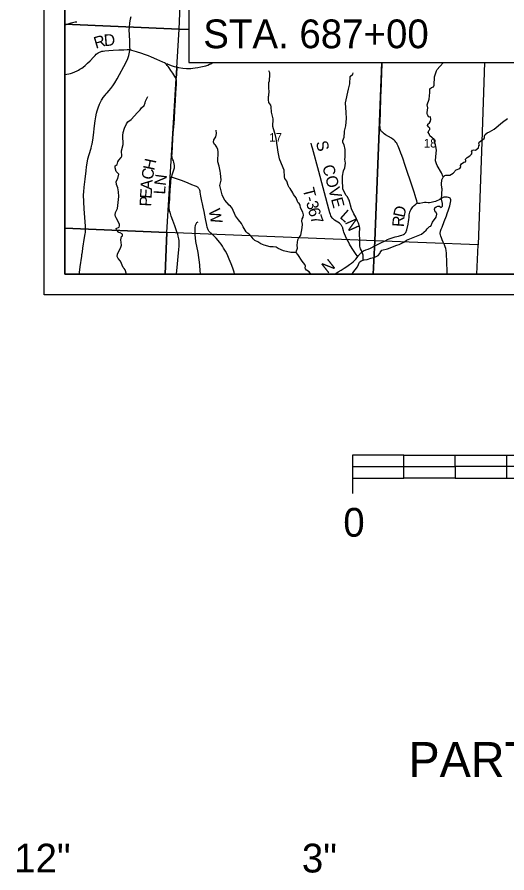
# Model space of a CAD drawing. Extents: x 0 to 34, y 0 to 22.
# Drawn here: x 23.784 to 26.169, y 11.185 to 15.353 of the extents above; entities that cross this region are included whole.
import ezdxf

# ---------------------------------------------------------------- set-up
doc = ezdxf.new("R2010")
doc.units = 0
for name, color, linetype in [('GM_X_Adjacent_County', 7, 'Continuous'), ('GM_X_County', 7, 'Continuous'), ('GM_X_County_Road', 7, 'Continuous'), ('GM_X_County_Road_Text', 7, 'Continuous'), ('GM_X_Minor_River', 7, 'Continuous'), ('GM_X_Section', 7, 'Continuous'), ('GM_X_Section_Text', 7, 'Continuous'), ('GM_X_Township', 7, 'Continuous'), ('GM_X_Township_Road', 7, 'Continuous'), ('GM_X_Township_Road_Text', 7, 'Continuous'), ('SH_Data', 7, 'Continuous'), ('SH_Text', 7, 'Continuous')]:
    doc.layers.add(name, color=color, linetype=linetype)

msp = doc.modelspace()

# ---------------------------------------------------------------- linework, layer by layer
at = {"layer": 'GM_X_Adjacent_County'}
msp.add_lwpolyline([(28.7526, 20.9), (24.0167, 20.9), (24.0167, 14.1), (28.5181, 14.1)], dxfattribs=at)
at = {"layer": 'GM_X_County'}
msp.add_lwpolyline([(28.7526, 20.9), (24.0167, 20.9), (24.0167, 14.1), (28.5181, 14.1)], dxfattribs=at)
at = {"layer": 'GM_X_County_Road'}
for points in [[(24.3339, 15.1942), (24.334, 15.1957), (24.3339, 15.2052), (24.3335, 15.2144), (24.3327, 15.233), (24.3309, 15.2671), (24.3307, 15.2888), (24.3315, 15.3043), (24.3335, 15.3227), (24.3371, 15.3442), (24.34, 15.3563)], [(24.0862, 14.1), (24.0874, 14.1082), (24.0915, 14.1358), (24.0991, 14.1877), (24.0996, 14.1931), (24.1002, 14.1969), (24.1009, 14.2018), (24.102, 14.2098), (24.1047, 14.2273), (24.1132, 14.2796), (24.116, 14.298), (24.1166, 14.304), (24.1173, 14.3102), (24.1176, 14.3195), (24.1173, 14.3275), (24.117, 14.3351), (24.111, 14.4188), (24.1088, 14.4529), (24.1083, 14.487), (24.1088, 14.5025), (24.1105, 14.5241), (24.1153, 14.5642), (24.1198, 14.6044), (24.1223, 14.6228), (24.1253, 14.6411), (24.1294, 14.6623), (24.1348, 14.6834), (24.1441, 14.7146), (24.1466, 14.7234), (24.1484, 14.7309), (24.1491, 14.7342), (24.1514, 14.7452), (24.1526, 14.7526), (24.1563, 14.7771), (24.1618, 14.8231), (24.1647, 14.8477), (24.1672, 14.8662), (24.1704, 14.8845), (24.1734, 14.8964), (24.1787, 14.9109), (24.1857, 14.9282), (24.1922, 14.9422), (24.1956, 14.9486), (24.1983, 14.9529), (24.2036, 14.9605), (24.2131, 14.9725), (24.2187, 14.9794), (24.2225, 14.984), (24.2324, 14.9955), (24.2405, 15.0049), (24.2499, 15.0173), (24.2602, 15.0328), (24.271, 15.0518), (24.2828, 15.0736), (24.3041, 15.1115), (24.3155, 15.1336), (24.3231, 15.1506), (24.3284, 15.1652), (24.3307, 15.1742), (24.3323, 15.1815), (24.3335, 15.1894), (24.3339, 15.1942)], [(24.5097, 15.1242), (24.5065, 15.1268), (24.5027, 15.1293), (24.494, 15.1334), (24.4785, 15.14), (24.4642, 15.1463), (24.4386, 15.1574), (24.4243, 15.1632), (24.404, 15.1708), (24.3923, 15.1748), (24.3657, 15.1832), (24.3425, 15.1906), (24.3339, 15.1942)], [(25.731, 14.4469), (25.7316, 14.4497), (25.7317, 14.4521), (25.7314, 14.4548), (25.7307, 14.4579), (25.7261, 14.4727), (25.7221, 14.4845), (25.7172, 14.4993), (25.7106, 14.52), (25.6723, 14.6346), (25.6636, 14.6608), (25.6573, 14.6782), (25.6527, 14.6897), (25.646, 14.7071), (25.6393, 14.7245), (25.6355, 14.7331), (25.6325, 14.7386), (25.6291, 14.7439), (25.6252, 14.7488), (25.6207, 14.7533), (25.6158, 14.7572), (25.608, 14.7624), (25.5786, 14.7797), (25.5709, 14.7848), (25.566, 14.7886), (25.5615, 14.7927), (25.5595, 14.795), (25.5576, 14.7974), (25.556, 14.7999), (25.5546, 14.8026), (25.5534, 14.8054), (25.5525, 14.8083), (25.5518, 14.8112), (25.5513, 14.8142), (25.551, 14.8263), (25.5518, 14.8388), (25.5535, 14.891), (25.5552, 14.9559), (25.5557, 14.9683), (25.5565, 14.9869), (25.5618, 15.1264), (25.5619, 15.131)], [(24.5582, 15.053), (24.552, 15.0638), (24.5418, 15.08), (24.5329, 15.0927), (24.5242, 15.1057), (24.5193, 15.1125), (24.5152, 15.1176), (24.5116, 15.1218), (24.5097, 15.1242)], [(24.5582, 15.053), (24.5604, 15.0579), (24.5609, 15.0624), (24.5615, 15.0678), (24.5617, 15.0756), (24.5619, 15.0816), (24.5626, 15.0905), (24.5631, 15.0964), (24.5639, 15.1014), (24.5654, 15.1073), (24.5656, 15.1081)], [(24.5362, 14.5738), (24.5407, 14.5887), (24.5473, 14.6093), (24.5501, 14.6181), (24.5508, 14.6234), (24.5508, 14.6304), (24.5497, 14.6385), (24.5473, 14.6463), (24.5452, 14.6523), (24.5429, 14.6571), (24.5408, 14.6617), (24.5396, 14.6652), (24.5387, 14.67), (24.5384, 14.6754), (24.5389, 14.6886), (24.5424, 14.7588), (24.5446, 14.7887), (24.547, 14.8178), (24.5484, 14.834), (24.55, 14.8564), (24.5524, 14.9006), (24.5532, 14.9209), (24.5548, 14.9478), (24.5576, 14.9829), (24.5589, 15.0046), (24.5606, 15.0258), (24.5606, 15.0368), (24.5598, 15.046), (24.5582, 15.053)], [(24.8429, 14.1), (24.8426, 14.1021), (24.8413, 14.1102), (24.8386, 14.1201), (24.8348, 14.1303), (24.8268, 14.1504), (24.8172, 14.1733), (24.8097, 14.1903), (24.8048, 14.201), (24.7989, 14.2126), (24.79, 14.2277), (24.7849, 14.2364), (24.7781, 14.2461), (24.7703, 14.2563), (24.7636, 14.2647), (24.7528, 14.276), (24.7393, 14.29), (24.7282, 14.2997), (24.7249, 14.3031), (24.7228, 14.3051), (24.72, 14.3082), (24.718, 14.3107), (24.7162, 14.3134), (24.7146, 14.3166), (24.7129, 14.321), (24.7116, 14.3248), (24.7105, 14.3289), (24.708, 14.3386), (24.7016, 14.3701), (24.6945, 14.4052), (24.6899, 14.4277), (24.6865, 14.4428), (24.6835, 14.4556), (24.6792, 14.4799), (24.6759, 14.5007), (24.6751, 14.5047), (24.6735, 14.5096), (24.6723, 14.5124), (24.6709, 14.5151), (24.6693, 14.5177), (24.6674, 14.5201), (24.6652, 14.5222), (24.6629, 14.5241), (24.6604, 14.5259), (24.6577, 14.5274), (24.6522, 14.5299), (24.6347, 14.5362), (24.6175, 14.5435), (24.589, 14.5555), (24.5746, 14.5609), (24.5514, 14.5689), (24.5362, 14.5738)], [(25.4434, 14.1867), (25.4471, 14.1916), (25.4527, 14.199), (25.4547, 14.2012), (25.4568, 14.2034), (25.459, 14.2053), (25.4627, 14.2082), (25.4665, 14.2106), (25.4715, 14.2138), (25.4825, 14.2186), (25.4937, 14.2231), (25.5049, 14.2282), (25.526, 14.2386), (25.555, 14.2533), (25.5759, 14.2639), (25.5881, 14.2695), (25.5954, 14.2728), (25.6049, 14.2765), (25.6156, 14.2799), (25.6258, 14.2827), (25.642, 14.2864), (25.6511, 14.2885), (25.658, 14.2909), (25.6655, 14.2941), (25.6705, 14.2972), (25.6746, 14.301), (25.6772, 14.3045), (25.6789, 14.3083), (25.6799, 14.3113), (25.6815, 14.3173), (25.6879, 14.3444), (25.6903, 14.3565), (25.6917, 14.3657), (25.6929, 14.378), (25.6941, 14.3902), (25.6952, 14.3962), (25.6967, 14.402), (25.6987, 14.4078), (25.7012, 14.4133), (25.7042, 14.4186), (25.7076, 14.4237), (25.7114, 14.4284), (25.7135, 14.4306), (25.7179, 14.4349), (25.7251, 14.4411), (25.729, 14.4444), (25.731, 14.4469)], [(25.3304, 14.1), (25.333, 14.102), (25.3403, 14.1076), (25.3481, 14.1128), (25.3614, 14.1207), (25.3774, 14.1303), (25.3904, 14.1388), (25.4032, 14.1476), (25.4132, 14.1551), (25.4204, 14.1611), (25.4273, 14.1674), (25.4338, 14.1742), (25.4397, 14.1815), (25.4434, 14.1867)]]:
    msp.add_lwpolyline(points, dxfattribs=at)
at = {"layer": 'GM_X_Minor_River'}
for points in [[(24.0167, 15.3131), (24.0234, 15.316), (24.0468, 15.3241), (24.0668, 15.3288), (24.0755, 15.33)], [(25.8595, 14.5752), (25.8511, 14.5936), (25.8297, 14.6295), (25.8258, 14.6382), (25.8223, 14.6534), (25.8225, 14.6735), (25.8257, 14.7042), (25.8237, 14.7217), (25.8148, 14.7561), (25.7938, 14.7738), (25.79, 14.7848), (25.7861, 14.7909), (25.7887, 14.8004), (25.7936, 14.805), (25.7936, 14.8125), (25.7886, 14.8159), (25.7833, 14.825), (25.7847, 14.8307), (25.7923, 14.8383), (25.7968, 14.8463), (25.7982, 14.8539), (25.7966, 14.8668), (25.7883, 14.8652), (25.7822, 14.8762), (25.7802, 14.8826), (25.7802, 14.8876), (25.7834, 14.9107), (25.7815, 14.9259), (25.79, 14.9533), (25.7932, 14.9855), (25.7938, 14.9969), (25.7938, 15.0026), (25.8017, 15.0102), (25.8112, 15.0133), (25.8157, 15.0213), (25.8169, 15.0612), (25.8262, 15.0908), (25.8299, 15.0973), (25.8419, 15.1122), (25.8608, 15.131)], [(25.2148, 14.1), (25.2056, 14.1122), (25.1927, 14.1208), (25.1881, 14.1261), (25.1869, 14.1318), (25.188, 14.139), (25.1853, 14.1477), (25.1719, 14.1643), (25.1512, 14.1964), (25.1436, 14.2055), (25.1439, 14.2142), (25.148, 14.2218), (25.1503, 14.2275), (25.1479, 14.2419), (25.1515, 14.2678), (25.1545, 14.2746), (25.1661, 14.291), (25.1731, 14.3263), (25.1745, 14.3449), (25.171, 14.3582), (25.1728, 14.37), (25.1769, 14.3791), (25.1791, 14.389), (25.1752, 14.4022), (25.1645, 14.4238), (25.1632, 14.4371), (25.1583, 14.445), (25.1529, 14.448), (25.1499, 14.4541), (25.1425, 14.4722), (25.1296, 14.4885), (25.1261, 14.4968), (25.1131, 14.5172), (25.1085, 14.5221), (25.1039, 14.5319), (25.0973, 14.5539), (25.0881, 14.5667), (25.0862, 14.5743), (25.0848, 14.6077), (25.0636, 14.6569), (25.0625, 14.6618), (25.0551, 14.6944), (25.0455, 14.7619), (25.0428, 14.7766), (25.0296, 14.8194), (25.0305, 14.8574), (25.0227, 14.8903), (25.0214, 14.9157), (25.019, 14.9241), (25.0102, 14.9373), (25.0083, 14.9494), (25.0089, 14.9657), (25.0096, 14.9707), (25.0118, 14.9912), (25.0098, 15.0048), (25.01, 15.034), (25.0129, 15.0428), (25.0154, 15.0724), (25.0153, 15.0819), (25.0092, 15.0902)], [(25.4688, 14.1692), (25.4698, 14.1935), (25.4609, 14.2166), (25.4559, 14.2246), (25.4536, 14.2367), (25.4526, 14.2636), (25.4509, 14.2997), (25.4534, 14.324), (25.4522, 14.3323), (25.4468, 14.349), (25.4414, 14.3596), (25.4337, 14.3781), (25.4241, 14.3943), (25.4129, 14.4197), (25.4005, 14.4614), (25.3982, 14.4667), (25.3929, 14.4769), (25.3856, 14.4863), (25.3699, 14.5169), (25.3681, 14.5594), (25.3687, 14.5776), (25.3731, 14.6035), (25.3805, 14.6187), (25.3838, 14.6411), (25.3806, 14.6616), (25.381, 14.6692), (25.3811, 14.7071), (25.3764, 14.7313), (25.3706, 14.7427), (25.3709, 14.7518), (25.3765, 14.7681), (25.3778, 14.7921), (25.3786, 14.7974), (25.3845, 14.8232), (25.3884, 14.8593), (25.3859, 14.8885), (25.3841, 14.9344), (25.3976, 15.002), (25.405, 15.0278), (25.4056, 15.0639), (25.4191, 15.075), (25.421, 15.081)], [(24.3171, 14.8334), (24.3235, 14.843), (24.3393, 14.8533), (24.3705, 14.8884), (24.3837, 14.9006), (24.3904, 14.9105), (24.4032, 14.9216), (24.4073, 14.9349), (24.4099, 14.944), (24.4207, 14.9657)], [(26.0019, 14.7054), (26.0075, 14.7065), (26.017, 14.7051), (26.0313, 14.7154), (26.0328, 14.7264), (26.035, 14.7314), (26.0331, 14.7363), (26.0349, 14.7439), (26.0591, 14.7607), (26.0605, 14.766), (26.0601, 14.7733), (26.0627, 14.7801), (26.0729, 14.7893), (26.0842, 14.7935), (26.1065, 14.8069), (26.1479, 14.8417), (26.1728, 14.8589)], [(24.3169, 14.1), (24.3106, 14.1212), (24.3052, 14.1276), (24.3002, 14.1333), (24.2883, 14.1647), (24.2765, 14.1779), (24.2719, 14.1874), (24.2729, 14.1988), (24.2774, 14.2094), (24.2879, 14.2269), (24.2919, 14.2425), (24.2887, 14.2679), (24.2932, 14.2835), (24.2981, 14.287), (24.2969, 14.2957), (24.2862, 14.3017), (24.2798, 14.3035), (24.2676, 14.3164), (24.2671, 14.3224), (24.2811, 14.3301), (24.283, 14.3362), (24.2829, 14.3449), (24.266, 14.3759), (24.2641, 14.382), (24.2614, 14.3903), (24.2628, 14.4013), (24.2725, 14.4211), (24.2801, 14.4788), (24.2784, 14.502), (24.2745, 14.5209), (24.2687, 14.5379), (24.2667, 14.5523), (24.2742, 14.5668), (24.2797, 14.5873), (24.2755, 14.5934), (24.2668, 14.6002), (24.2625, 14.6187), (24.2624, 14.629), (24.2715, 14.6347), (24.2744, 14.648), (24.2797, 14.6564), (24.2917, 14.669), (24.2939, 14.6755), (24.2926, 14.7012), (24.3, 14.7324), (24.2989, 14.7756), (24.3011, 14.7901), (24.3078, 14.8125), (24.3171, 14.8334)], [(25.1436, 14.2055), (25.1175, 14.2057), (25.0818, 14.2142), (25.0552, 14.2258), (25.0449, 14.2322), (25.0309, 14.2344), (25.0165, 14.2335), (24.9869, 14.2413), (24.9714, 14.248), (24.9565, 14.2582), (24.9425, 14.2645), (24.9337, 14.2721), (24.9245, 14.2853), (24.915, 14.2951), (24.9066, 14.3), (24.8994, 14.3064), (24.8844, 14.3306), (24.8764, 14.3476), (24.8622, 14.3653), (24.8576, 14.3725), (24.8485, 14.3846), (24.8308, 14.422), (24.8232, 14.4319), (24.8174, 14.436), (24.7953, 14.4617), (24.7892, 14.4726), (24.7826, 14.4874), (24.7717, 14.5328), (24.7787, 14.5587), (24.7747, 14.5928), (24.7735, 14.6023), (24.7684, 14.6265), (24.7615, 14.647), (24.7627, 14.6963), (24.7611, 14.7073), (24.7572, 14.7194), (24.7507, 14.7292), (24.7457, 14.733), (24.7411, 14.744), (24.743, 14.7542), (24.7516, 14.7698), (24.7545, 14.7862), (24.7529, 14.8013)], [(25.4104, 14.1), (25.4193, 14.1067), (25.4425, 14.1361), (25.4522, 14.1585), (25.4594, 14.1661), (25.4737, 14.1708), (25.4889, 14.1728), (25.5066, 14.1793), (25.5255, 14.184), (25.5418, 14.1913), (25.5497, 14.2013), (25.5515, 14.2062), (25.5601, 14.2169), (25.5881, 14.2239), (25.6327, 14.2428), (25.644, 14.2447), (25.6712, 14.2586), (25.681, 14.2658), (25.6961, 14.2735), (25.7535, 14.2963), (25.7754, 14.3158), (25.781, 14.3215), (25.7927, 14.3333), (25.798, 14.3353), (25.8073, 14.3543), (25.8249, 14.3783), (25.8282, 14.3928), (25.824, 14.4007), (25.8191, 14.4041), (25.8167, 14.4158), (25.8189, 14.4246), (25.8242, 14.4288), (25.8329, 14.4319), (25.8408, 14.4319), (25.8488, 14.4255), (25.8552, 14.4312), (25.8552, 14.4449), (25.8512, 14.4665), (25.8535, 14.5158), (25.8531, 14.5219), (25.8511, 14.5386), (25.8525, 14.5602), (25.8581, 14.5739), (25.8671, 14.582), (25.8724, 14.5835), (25.8906, 14.5825), (25.9068, 14.5928), (25.9218, 14.6096), (25.9396, 14.615), (25.9445, 14.6238), (25.9433, 14.6295), (25.9474, 14.6375), (25.9591, 14.6463), (25.9682, 14.6482), (25.9696, 14.6532), (25.9677, 14.6611), (25.9756, 14.6695), (25.9884, 14.6772), (25.9967, 14.6845), (25.9997, 14.6905), (25.9974, 14.6958), (26.0019, 14.7054)], [(24.6771, 14.1), (24.6749, 14.1201), (24.6744, 14.1418), (24.6744, 14.1467), (24.6656, 14.2062), (24.6546, 14.26), (24.6514, 14.2934), (24.6512, 14.3272), (24.653, 14.3401), (24.6601, 14.3523), (24.6657, 14.355)]]:
    msp.add_lwpolyline(points, dxfattribs=at)
at = {"layer": 'GM_X_Section'}
for p, q in [((24.0167, 16.3224), (24.0167, 15.3189)), ((24.0167, 15.3189), (24.0167, 14.3246)), ((24.5057, 14.1), (25.5188, 14.1)), ((25.5188, 14.1), (26.0222, 14.1))]:
    msp.add_line(p, q, dxfattribs=at)
for points in [[(24.0167, 15.3189), (24.5727, 15.2931), (24.6148, 16.293), (24.0167, 16.3224)], [(24.6207, 15.2914), (24.5727, 15.2931), (24.6148, 16.293), (25.601, 16.254), (25.5786, 15.621)], [(24.0167, 14.3246), (24.5132, 14.3029), (24.5727, 15.2931), (24.0167, 15.3189)], [(25.5607, 15.131), (25.526, 14.2636), (24.5132, 14.3029), (24.5727, 15.2931), (24.6207, 15.2914)], [(26.06, 15.131), (26.0465, 14.7451), (26.029, 14.244), (25.526, 14.2636), (25.5607, 15.131)], [(24.0167, 14.3246), (24.0167, 14.1), (24.5057, 14.1)], [(24.5057, 14.1), (24.5132, 14.3029), (24.0167, 14.3246)], [(25.5188, 14.1), (25.526, 14.2636), (24.5132, 14.3029), (24.5057, 14.1)], [(26.0222, 14.1), (26.029, 14.244), (25.526, 14.2636), (25.5188, 14.1)]]:
    msp.add_lwpolyline(points, dxfattribs=at)
at = {"layer": 'GM_X_Township'}
msp.add_lwpolyline([(24.0167, 18.4402), (24.0167, 14.1), (28.5181, 14.1)], dxfattribs=at)
at = {"layer": 'GM_X_Township_Road'}
for points in [[(24.0167, 15.0725), (24.0267, 15.0739), (24.0358, 15.0756), (24.0448, 15.0778), (24.0535, 15.0807), (24.065, 15.0854), (24.0762, 15.0906), (24.0829, 15.0941), (24.0904, 15.0984), (24.0988, 15.1041), (24.1064, 15.1095), (24.115, 15.1168), (24.1274, 15.1278), (24.1393, 15.1394), (24.1568, 15.158), (24.1638, 15.1656), (24.1694, 15.1713), (24.1743, 15.1753), (24.1795, 15.1788), (24.185, 15.1817), (24.1908, 15.1841), (24.1968, 15.1859), (24.2029, 15.1873), (24.2121, 15.1886), (24.2305, 15.1905), (24.2521, 15.1923), (24.28, 15.1928), (24.2923, 15.1931), (24.3046, 15.194), (24.32, 15.1952), (24.3261, 15.1954), (24.3291, 15.1951), (24.3339, 15.1942)], [(24.5656, 15.1081), (24.5699, 15.1073), (24.5918, 15.1042), (24.6088, 15.103), (24.6181, 15.1027), (24.6305, 15.1029), (24.6398, 15.1035), (24.6521, 15.1049), (24.6644, 15.1069), (24.6797, 15.1099), (24.6948, 15.1134), (24.7038, 15.116), (24.7126, 15.119), (24.7212, 15.1226), (24.7268, 15.1253), (24.7322, 15.1282), (24.7369, 15.131), (24.7369, 15.131)], [(24.5097, 15.1242), (24.5104, 15.1244), (24.512, 15.1247), (24.5137, 15.1248), (24.5149, 15.1246), (24.5166, 15.1244), (24.5185, 15.1238), (24.5396, 15.1156), (24.5484, 15.1127), (24.5572, 15.1102), (24.5632, 15.1086), (24.5656, 15.1081)], [(25.4434, 14.1867), (25.4403, 14.1906), (25.4351, 14.1972), (25.4261, 14.2108), (25.416, 14.2263), (25.4035, 14.2474), (25.3958, 14.2607), (25.3885, 14.2743), (25.3832, 14.2854), (25.3783, 14.2967), (25.3751, 14.3054), (25.3733, 14.3113), (25.3704, 14.3234), (25.3696, 14.3264), (25.3685, 14.3293), (25.3673, 14.3321), (25.3658, 14.3349), (25.3642, 14.3375), (25.3624, 14.34), (25.3603, 14.3424), (25.3582, 14.3446), (25.3534, 14.3486), (25.3457, 14.3539), (25.3302, 14.3643), (25.3252, 14.3679), (25.3228, 14.3699), (25.3206, 14.3721), (25.3187, 14.3745), (25.3151, 14.3796), (25.3121, 14.385), (25.3098, 14.391), (25.3068, 14.3996), (25.3015, 14.4175), (25.2531, 14.6007), (25.2219, 14.7145), (25.2196, 14.7236), (25.2167, 14.7388)], [(24.5599, 14.1), (24.5647, 14.1509), (24.5682, 14.1868), (24.5717, 14.2209), (24.573, 14.2372), (24.5735, 14.2464), (24.5735, 14.2559), (24.573, 14.265), (24.5717, 14.2735), (24.5688, 14.2861), (24.5663, 14.295), (24.5625, 14.3068), (24.5519, 14.336), (24.5425, 14.3622), (24.5352, 14.3827), (24.529, 14.402), (24.527, 14.4081), (24.5257, 14.4141), (24.5248, 14.4203), (24.5247, 14.4251), (24.5251, 14.4362), (24.5261, 14.4492), (24.5276, 14.4678), (24.5284, 14.4768), (24.5294, 14.5113), (24.5306, 14.5299), (24.5321, 14.5453), (24.5335, 14.5576), (24.5362, 14.5738)], [(25.878, 14.1), (25.8782, 14.1189), (25.8775, 14.154), (25.877, 14.1633), (25.8762, 14.1757), (25.8758, 14.1847), (25.8744, 14.2031), (25.8728, 14.2166), (25.8712, 14.2257), (25.869, 14.2337), (25.865, 14.2431), (25.8587, 14.257), (25.8539, 14.2684), (25.8504, 14.277), (25.8473, 14.2858), (25.8456, 14.2917), (25.845, 14.2948), (25.8447, 14.2979), (25.8446, 14.301), (25.8448, 14.304), (25.8453, 14.3071), (25.8461, 14.3101), (25.8494, 14.3192), (25.8534, 14.3295), (25.8636, 14.3567), (25.8743, 14.3846), (25.8785, 14.3961), (25.8844, 14.4135), (25.8906, 14.4337), (25.8952, 14.45), (25.8961, 14.4573), (25.8963, 14.4603), (25.896, 14.4635), (25.8949, 14.467), (25.8926, 14.4701), (25.889, 14.4726), (25.8842, 14.4746), (25.8789, 14.4757), (25.8725, 14.4761), (25.8664, 14.4758), (25.8616, 14.4751), (25.8554, 14.4729), (25.8496, 14.4699), (25.8424, 14.4652), (25.8357, 14.4609), (25.8283, 14.4574), (25.8214, 14.4548), (25.814, 14.4523), (25.8011, 14.4492), (25.7931, 14.4485), (25.7861, 14.4485), (25.7763, 14.4492), (25.7684, 14.4491), (25.7591, 14.4479), (25.7459, 14.4451), (25.7418, 14.4448), (25.7382, 14.4448), (25.7349, 14.4453), (25.7325, 14.4462), (25.731, 14.4469)]]:
    msp.add_lwpolyline(points, dxfattribs=at)
at = {"layer": 'SH_Data'}
for p, q in [((25.6667, 13.22), (25.4167, 13.22)), ((25.4167, 13.22), (25.4167, 13.1638)), ((25.6667, 13.22), (25.9167, 13.22)), ((25.6667, 13.1638), (25.6667, 13.22)), ((25.9167, 13.1638), (25.9167, 13.22)), ((25.9167, 13.22), (26.1667, 13.22)), ((26.1667, 13.22), (26.4167, 13.22)), ((26.1667, 13.22), (26.1667, 13.1638)), ((25.4167, 13.1638), (25.4167, 13.0325)), ((25.4167, 13.1638), (25.6667, 13.1638)), ((25.6667, 13.1638), (25.9167, 13.1638)), ((25.6667, 13.1075), (25.6667, 13.1638)), ((25.9167, 13.1638), (25.9167, 13.1075)), ((26.1667, 13.1638), (25.9167, 13.1638)), ((26.4167, 13.1638), (26.1667, 13.1638)), ((26.1667, 13.1638), (26.1667, 13.1075)), ((25.4167, 13.1075), (25.6667, 13.1075)), ((25.9167, 13.1075), (25.6667, 13.1075)), ((25.9167, 13.1075), (26.1667, 13.1075)), ((26.1667, 13.1075), (26.4167, 13.1075))]:
    msp.add_line(p, q, dxfattribs=at)
for points in [[(23.9167, 21), (30.9167, 21), (30.9167, 14), (23.9167, 14)], [(24.0167, 20.9), (30.8167, 20.9), (30.8167, 14.1), (24.0167, 14.1)]]:
    msp.add_lwpolyline(points, close=True, dxfattribs=at)
at = {"layer": 'SH_Text'}
msp.add_lwpolyline([(24.6207, 15.131), (26.3766, 15.131), (26.3766, 15.621), (24.6207, 15.621)], close=True, dxfattribs=at)

# ---------------------------------------------------------------- texts
at = {"layer": 'GM_X_County_Road_Text'}
for s, rotation, p in [('W', 280.8943, (24.7163, 14.4138)), ('D', 77.8663, (25.6701, 14.3735)), ('R', 85.9611, (25.6672, 14.3291)), ('N', 38.1785, (25.2952, 14.1009))]:
    msp.add_text(s, height=0.0568, rotation=rotation, dxfattribs=at).set_placement(p)
at = {"layer": 'GM_X_Section_Text'}
for s, p in [('17', (25.0118, 14.7456)), ('18', (25.7643, 14.7176))]:
    msp.add_text(s, height=0.04186, rotation=0, dxfattribs=at).set_placement(p)
at = {"layer": 'GM_X_Township_Road_Text'}
for s, height, rotation, p in [('R', 0.0568, 16.34, (24.1672, 15.1982)), ('D', 0.0568, 4.9494, (24.2091, 15.2107)), ('S', 0.0568, 284.2195, (25.2384, 14.7432)), ('H', 0.0568, 78.0528, (24.4522, 14.6032)), ('COVE', 0.05682, 284.9151, (25.2697, 14.6258)), ('C', 0.0568, 79.9647, (24.4441, 14.5577)), ('A', 0.0568, 86.5554, (24.4413, 14.5095)), ('N', 0.0568, 82.5587, (24.5075, 14.5294)), ('E', 0.0568, 86.5867, (24.4388, 14.4671)), ('L', 0.0568, 86.14, (24.5047, 14.4879)), ('T', 0.0568, 284.5913, (25.1743, 14.5143)), ('P', 0.0568, 86.5864, (24.4365, 14.4289)), ('-', 0.0568, 284.6184, (25.185, 14.4732)), ('3', 0.0568, 284.7148, (25.1909, 14.4505)), ('6', 0.0568, 285.2046, (25.1999, 14.4161)), ('7', 0.0568, 289.5475, (25.2105, 14.3779)), ('L', 0.0568, 318.3472, (25.3516, 14.3776)), ('N', 0.0568, 294.2887, (25.3797, 14.3544))]:
    msp.add_text(s, height=height, rotation=rotation, dxfattribs=at).set_placement(p)
at = {"layer": 'SH_Text'}
for s, height, p in [('STA. 687+00', 0.14, (24.6907, 15.201)), ('0', 0.14, (25.3726, 12.8225)), ('PARTICLE SIZE DEFINITIONS', 0.17, (25.6902, 11.6525)), ('12"', 0.14, (23.7701, 11.1873)), ('3"', 0.14, (25.1709, 11.1873))]:
    msp.add_text(s, height=height, dxfattribs=at).set_placement(p)

doc.saveas('drawing.dxf')
